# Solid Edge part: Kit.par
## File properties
Dokumentum tartalom típus: 0
Last saved by: bmolnar
Revision: 77
Sűrűség: 0,000 kg/m^3
Pontosság: 0,990
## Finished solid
Body 1: solid body, 19 faces, 28 edges, 22 vertices.
  Faces by surface: plane 9, cylinder 6, torus 3, cone 1
  Edges by curve: circle 18, line 10
Body 2: solid body, 5 faces, 9 edges, 5 vertices.
  Faces by surface: spun 2, torus 2, plane 1
  Edges by curve: curve on surface 6, ellipse 2, circle 1
Bounding box of the edges (mm; curved faces can reach further): 14.800 x 14.250 x 2.452, from (-7.4, -6.85, 33.9478) to (7.4, 7.4, 36.4).
Cylindrical faces by radius (mm): R3 x1, R4.675 x1, R5.6 x1, R6.1 x1, R6.85 x1, R7.4 x1
Conical faces (half-angle, radius in mm at the cone's reference point): 45 deg R5.45 x1
Toroidal faces (ring radius, tube radius in mm): R3.6157 r1.0574 x1, R4.0606 r1.0588 x1, R4.475 r0.2 x2, R5.8 r0.2 x1
Planar faces by outward normal: +z 3, -z 5, oblique 2
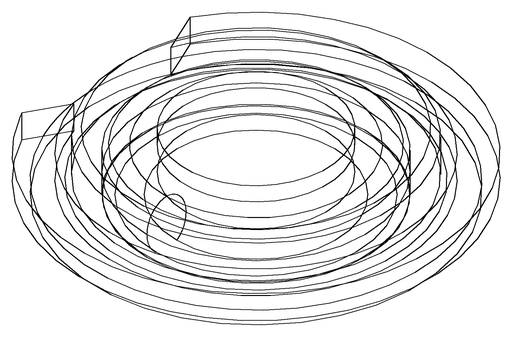
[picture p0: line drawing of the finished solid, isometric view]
